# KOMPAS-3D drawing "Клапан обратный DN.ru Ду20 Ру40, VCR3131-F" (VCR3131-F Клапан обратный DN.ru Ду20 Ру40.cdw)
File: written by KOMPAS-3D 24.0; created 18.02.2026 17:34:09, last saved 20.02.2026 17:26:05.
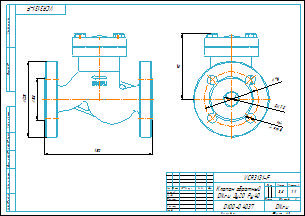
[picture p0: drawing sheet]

Document properties: арт: D100-04037; Автор: R2D2; Форматы листов документа: A3; Полное имя файла: VCR3131-F Клапан обратный DN.ru Ду20 Ру40.m3d; Масса: 3.8; Наименование: Клапан обратный DN.ru Ду20 Ру40; Количество листов документа: 1; Примечание: D100-04037

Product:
- Body: Тело 3  | qty 1
    Масса: 4.829539
- Part/product: Клапан обратный DN.ru Ду20 Ру40  | designation VCR3131-F
    Масса: 3.8
    Форматы листов документа: A3
    Примечание: D100-04037
    additional columns: D100-04037

Views: Вид 1, Спереди, Проекционный вид 2
Referenced files in E:\Работа\Зайцев\VCR3131-F Клапан обратный DN.ru Ду15-300\DN20\: VCR3131-F Клапан обратный DN.ru Ду20 Ру40.m3d
Referenced files in E:\Работа\Зайцев\Для компаса\: чертеж DN.ru А3.cdt
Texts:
  VCR3131-F
  чертеж DN.ru А3.cdt
  Клапан обратный
  DN.ru Ду20 Ру40
  prop
  Клапан обратный DN.ru Ду20 Ру40
  VCR3131-F Клапан обратный DN.ru Ду20 Ру40
Dimensions and other numbers on the sheet: 0; 3; 2; 4; 90; 14; 4 отв.; 75; 20; 150; 105; 58; 1:1; 1; 3,8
